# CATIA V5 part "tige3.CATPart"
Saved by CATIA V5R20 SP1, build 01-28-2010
Part number: tige3
Bounding box of the stored display mesh (mm): x -18.695 to -7.5, y -67.5 to 635.025, z -10 to 10
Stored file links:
  C:\Users\Fox\Desktop\IAO Projet\A RENDRE\Sauvegarde IFMA\tige3.CATPart
  C:\Users\Fox\Desktop\IAO Projet\A RENDRE\Sauvegarde IFMA\mpeyrard.CATProduct
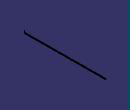
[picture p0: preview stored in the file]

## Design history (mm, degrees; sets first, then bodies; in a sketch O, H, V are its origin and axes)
Set1
  Plane1: linked copy from another document
  Line1 to Line3: linked copy from another document
Body1 (main body)
  Sketch1 on Plane1, origin (0, 0, 0), H (1, 0, 0), V (0, 1, 0)
    axis line L1 (-2.1705, -65) -> (-17.3498, -65)
    reference projected line E1 (0, -90) -> (0, -65) from Line1
    reference projected point E2 (0, -65) from Line2
    circle A1 centre (-10, -65) radius 2.5
    point P3 (-10, -65)
    reference projected point E3 (0, -65) from Line2
    distance L1 E2 = 0
    radius A1 = 2.5
    distance P3 E3 = 10
    perpendicularity: E1 L1
    coincidence: P3 L1
  Pad1: profile Sketch1, direction (0, 0, 1), length 10, mirrored extent
  Sketch2 on start face of Pad1, origin (0, 0, -10), H (1, 0, 0), V (0, -1, 0)
    line L1 (-12.5005, 65) -> (-7.5003, 65)
    line L2 (-7.5003, 65) -> (-13.6952, -635.0251)
    line L3 (-13.6952, -635.0251) -> (-18.6949, -634.9726)
    line L4 (-18.6949, -634.9726) -> (-12.5005, 65)
    reference projected line E1 through (-0.5751, 0.0141) direction (-0.0088, -1) from Line3
    axis line L5 (-6.2644, 65) -> (-25.9002, 65)
    reference projected line E2 (0, 90) -> (0, 65) from Line1
    reference projected point E3 (0, 65) from Line2
    reference projected line E4 through (-0.5751, 0.0141) direction (-0.0088, -1) from Line3
    distance L5 E3 = 0
    distance L2 E4 = 7.5
    length L3 = 5
    length L4 = 700
    parallelism: L2 L4, E1 L2, L1 L5
    perpendicularity: E2 L5
    coincidence: L1 L5
  Pad2: profile Sketch2, direction (0, 0, 1), length 6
